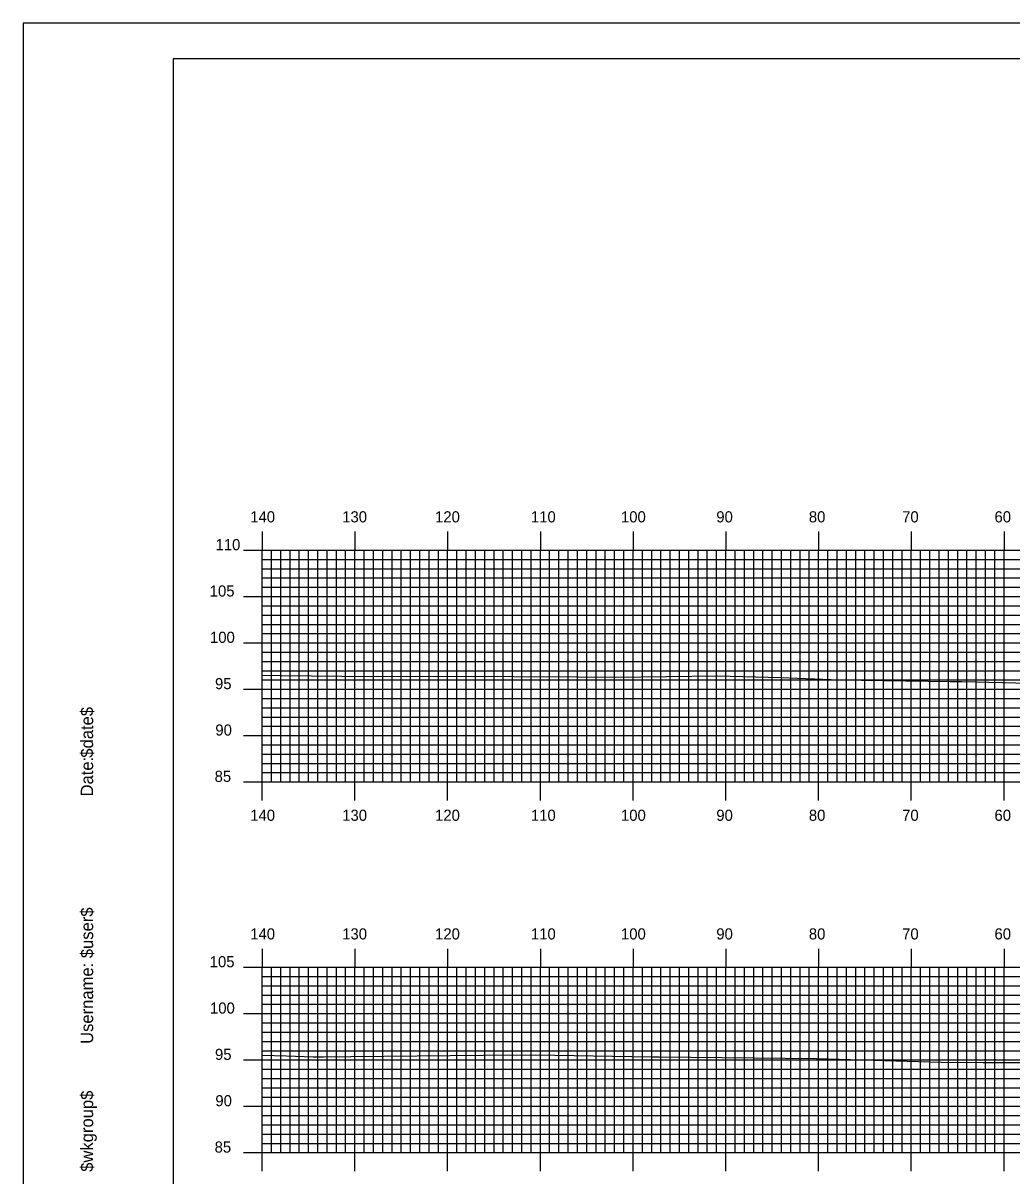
# Model space of a CAD drawing. Extents: x 1764152 to 1764495, y 442591 to 442811.
# Drawn here: x 1764152 to 1764258.7, y 442686.2 to 442810.5 of the extents above; entities that cross this region are included whole.
import ezdxf

# ---------------------------------------------------------------- set-up
doc = ezdxf.new("R2010")
doc.units = 0
for name, color, linetype in [('BORDER', 7, 'Continuous'), ('H_V ANNOTATION', 7, 'Continuous'), ('MAJOR', 7, 'Continuous'), ('MINOR', 7, 'Continuous'), ('PLOT BOUNDARY', 7, 'Continuous'), ('S_Roadway_Centerline', 7, 'Continuous')]:
    doc.layers.add(name, color=color, linetype=linetype)

msp = doc.modelspace()

# ---------------------------------------------------------------- linework, layer by layer
at = {"layer": 'BORDER'}
msp.add_lwpolyline([(1764168.23, 442596.67), (1764488.23, 442596.67), (1764488.23, 442806.67), (1764168.23, 442806.67)], close=True, dxfattribs=at)
at = {"layer": 'MAJOR'}
for p, q in [((1764177.83, 442755.67), (1764177.83, 442753.67)), ((1764187.83, 442755.67), (1764187.83, 442753.67)), ((1764197.83, 442755.67), (1764197.83, 442753.67)), ((1764207.83, 442755.67), (1764207.83, 442753.67)), ((1764217.83, 442755.67), (1764217.83, 442753.67)), ((1764227.83, 442755.67), (1764227.83, 442753.67)), ((1764237.83, 442755.67), (1764237.83, 442753.67)), ((1764247.83, 442755.67), (1764247.83, 442753.67)), ((1764257.83, 442755.67), (1764257.83, 442753.67)), ((1764175.83, 442753.67), (1764177.83, 442753.67)), ((1764177.83, 442753.67), (1764457.83, 442753.67)), ((1764177.83, 442728.67), (1764177.83, 442753.67)), ((1764177.83, 442728.67), (1764177.83, 442753.67)), ((1764177.83, 442753.67), (1764457.83, 442753.67)), ((1764187.83, 442728.67), (1764187.83, 442753.67)), ((1764197.83, 442728.67), (1764197.83, 442753.67)), ((1764207.83, 442728.67), (1764207.83, 442753.67)), ((1764217.83, 442728.67), (1764217.83, 442753.67)), ((1764227.83, 442728.67), (1764227.83, 442753.67)), ((1764237.83, 442728.67), (1764237.83, 442753.67)), ((1764247.83, 442728.67), (1764247.83, 442753.67)), ((1764257.83, 442728.67), (1764257.83, 442753.67)), ((1764175.83, 442748.67), (1764177.83, 442748.67)), ((1764177.83, 442748.67), (1764457.83, 442748.67)), ((1764175.83, 442743.67), (1764177.83, 442743.67)), ((1764177.83, 442743.67), (1764457.83, 442743.67)), ((1764175.83, 442738.67), (1764177.83, 442738.67)), ((1764177.83, 442738.67), (1764457.83, 442738.67)), ((1764175.83, 442733.67), (1764177.83, 442733.67)), ((1764177.83, 442733.67), (1764457.83, 442733.67)), ((1764175.83, 442728.67), (1764177.83, 442728.67)), ((1764177.83, 442728.67), (1764457.83, 442728.67)), ((1764177.83, 442728.67), (1764457.83, 442728.67)), ((1764177.83, 442726.66), (1764177.83, 442728.67)), ((1764187.83, 442726.66), (1764187.83, 442728.67)), ((1764197.83, 442726.66), (1764197.83, 442728.67)), ((1764207.83, 442726.66), (1764207.83, 442728.67)), ((1764217.83, 442726.66), (1764217.83, 442728.67)), ((1764227.83, 442726.66), (1764227.83, 442728.67)), ((1764237.83, 442726.66), (1764237.83, 442728.67)), ((1764247.83, 442726.66), (1764247.83, 442728.67)), ((1764257.83, 442726.66), (1764257.83, 442728.67)), ((1764177.83, 442710.67), (1764177.83, 442708.67)), ((1764187.83, 442710.67), (1764187.83, 442708.67)), ((1764197.83, 442710.67), (1764197.83, 442708.67)), ((1764207.83, 442710.67), (1764207.83, 442708.67)), ((1764217.83, 442710.67), (1764217.83, 442708.67)), ((1764227.83, 442710.67), (1764227.83, 442708.67)), ((1764237.83, 442710.67), (1764237.83, 442708.67)), ((1764247.83, 442710.67), (1764247.83, 442708.67)), ((1764257.83, 442710.67), (1764257.83, 442708.67)), ((1764175.83, 442708.67), (1764177.83, 442708.67)), ((1764177.83, 442708.67), (1764457.83, 442708.67)), ((1764177.83, 442688.67), (1764177.83, 442708.67)), ((1764177.83, 442688.67), (1764177.83, 442708.67)), ((1764177.83, 442708.67), (1764457.83, 442708.67)), ((1764187.83, 442688.67), (1764187.83, 442708.67)), ((1764197.83, 442688.67), (1764197.83, 442708.67)), ((1764207.83, 442688.67), (1764207.83, 442708.67)), ((1764217.83, 442688.67), (1764217.83, 442708.67)), ((1764227.83, 442688.67), (1764227.83, 442708.67)), ((1764237.83, 442688.67), (1764237.83, 442708.67)), ((1764247.83, 442688.67), (1764247.83, 442708.67)), ((1764257.83, 442688.67), (1764257.83, 442708.67)), ((1764175.83, 442703.67), (1764177.83, 442703.67)), ((1764177.83, 442703.67), (1764457.83, 442703.67)), ((1764175.83, 442698.67), (1764177.83, 442698.67)), ((1764177.83, 442698.67), (1764457.83, 442698.67)), ((1764175.83, 442693.67), (1764177.83, 442693.67)), ((1764177.83, 442693.67), (1764457.83, 442693.67)), ((1764175.83, 442688.67), (1764177.83, 442688.67)), ((1764177.83, 442688.67), (1764457.83, 442688.67)), ((1764177.83, 442688.67), (1764457.83, 442688.67)), ((1764177.83, 442686.66), (1764177.83, 442688.67)), ((1764187.83, 442686.66), (1764187.83, 442688.67)), ((1764197.83, 442686.66), (1764197.83, 442688.67)), ((1764207.83, 442686.66), (1764207.83, 442688.67)), ((1764217.83, 442686.66), (1764217.83, 442688.67)), ((1764227.83, 442686.66), (1764227.83, 442688.67)), ((1764237.83, 442686.66), (1764237.83, 442688.67)), ((1764247.83, 442686.66), (1764247.83, 442688.67)), ((1764257.83, 442686.66), (1764257.83, 442688.67))]:
    msp.add_line(p, q, dxfattribs=at)
at = {"layer": 'MINOR'}
for p, q in [((1764178.83, 442728.67), (1764178.83, 442753.67)), ((1764179.83, 442728.67), (1764179.83, 442753.67)), ((1764180.83, 442728.67), (1764180.83, 442753.67)), ((1764181.83, 442728.67), (1764181.83, 442753.67)), ((1764182.83, 442728.67), (1764182.83, 442753.67)), ((1764183.83, 442728.67), (1764183.83, 442753.67)), ((1764184.83, 442728.67), (1764184.83, 442753.67)), ((1764185.83, 442728.67), (1764185.83, 442753.67)), ((1764186.83, 442728.67), (1764186.83, 442753.67)), ((1764188.83, 442728.67), (1764188.83, 442753.67)), ((1764189.83, 442728.67), (1764189.83, 442753.67)), ((1764190.83, 442728.67), (1764190.83, 442753.67)), ((1764191.83, 442728.67), (1764191.83, 442753.67)), ((1764192.83, 442728.67), (1764192.83, 442753.67)), ((1764193.83, 442728.67), (1764193.83, 442753.67)), ((1764194.83, 442728.67), (1764194.83, 442753.67)), ((1764195.83, 442728.67), (1764195.83, 442753.67)), ((1764196.83, 442728.67), (1764196.83, 442753.67)), ((1764198.83, 442728.67), (1764198.83, 442753.67)), ((1764199.83, 442728.67), (1764199.83, 442753.67)), ((1764200.83, 442728.67), (1764200.83, 442753.67)), ((1764201.83, 442728.67), (1764201.83, 442753.67)), ((1764202.83, 442728.67), (1764202.83, 442753.67)), ((1764203.83, 442728.67), (1764203.83, 442753.67)), ((1764204.83, 442728.67), (1764204.83, 442753.67)), ((1764205.83, 442728.67), (1764205.83, 442753.67)), ((1764206.83, 442728.67), (1764206.83, 442753.67)), ((1764208.83, 442728.67), (1764208.83, 442753.67)), ((1764209.83, 442728.67), (1764209.83, 442753.67)), ((1764210.83, 442728.67), (1764210.83, 442753.67)), ((1764211.83, 442728.67), (1764211.83, 442753.67)), ((1764212.83, 442728.67), (1764212.83, 442753.67)), ((1764213.83, 442728.67), (1764213.83, 442753.67)), ((1764214.83, 442728.67), (1764214.83, 442753.67)), ((1764215.83, 442728.67), (1764215.83, 442753.67)), ((1764216.83, 442728.67), (1764216.83, 442753.67)), ((1764218.83, 442728.67), (1764218.83, 442753.67)), ((1764219.83, 442728.67), (1764219.83, 442753.67)), ((1764220.83, 442728.67), (1764220.83, 442753.67)), ((1764221.83, 442728.67), (1764221.83, 442753.67)), ((1764222.83, 442728.67), (1764222.83, 442753.67)), ((1764223.83, 442728.67), (1764223.83, 442753.67)), ((1764224.83, 442728.67), (1764224.83, 442753.67)), ((1764225.83, 442728.67), (1764225.83, 442753.67)), ((1764226.83, 442728.67), (1764226.83, 442753.67)), ((1764228.83, 442728.67), (1764228.83, 442753.67)), ((1764229.83, 442728.67), (1764229.83, 442753.67)), ((1764230.83, 442728.67), (1764230.83, 442753.67)), ((1764231.83, 442728.67), (1764231.83, 442753.67)), ((1764232.83, 442728.67), (1764232.83, 442753.67)), ((1764233.83, 442728.67), (1764233.83, 442753.67)), ((1764234.83, 442728.67), (1764234.83, 442753.67)), ((1764235.83, 442728.67), (1764235.83, 442753.67)), ((1764236.83, 442728.67), (1764236.83, 442753.67)), ((1764238.83, 442728.67), (1764238.83, 442753.67)), ((1764239.83, 442728.67), (1764239.83, 442753.67)), ((1764240.83, 442728.67), (1764240.83, 442753.67)), ((1764241.83, 442728.67), (1764241.83, 442753.67)), ((1764242.83, 442728.67), (1764242.83, 442753.67)), ((1764243.83, 442728.67), (1764243.83, 442753.67)), ((1764244.83, 442728.67), (1764244.83, 442753.67)), ((1764245.83, 442728.67), (1764245.83, 442753.67)), ((1764246.83, 442728.67), (1764246.83, 442753.67)), ((1764248.83, 442728.67), (1764248.83, 442753.67)), ((1764249.83, 442728.67), (1764249.83, 442753.67)), ((1764250.83, 442728.67), (1764250.83, 442753.67)), ((1764251.83, 442728.67), (1764251.83, 442753.67)), ((1764252.83, 442728.67), (1764252.83, 442753.67)), ((1764253.83, 442728.67), (1764253.83, 442753.67)), ((1764254.83, 442728.67), (1764254.83, 442753.67)), ((1764255.83, 442728.67), (1764255.83, 442753.67)), ((1764256.83, 442728.67), (1764256.83, 442753.67)), ((1764177.83, 442752.67), (1764457.83, 442752.67)), ((1764177.83, 442752.67), (1764179.84, 442752.67)), ((1764177.83, 442751.67), (1764457.83, 442751.67)), ((1764177.83, 442751.67), (1764179.84, 442751.67)), ((1764177.83, 442750.67), (1764457.83, 442750.67)), ((1764177.83, 442750.67), (1764179.84, 442750.67)), ((1764177.83, 442749.67), (1764457.83, 442749.67)), ((1764177.83, 442749.67), (1764179.84, 442749.67)), ((1764177.83, 442747.67), (1764457.83, 442747.67)), ((1764177.83, 442747.67), (1764179.84, 442747.67)), ((1764177.83, 442746.67), (1764457.83, 442746.67)), ((1764177.83, 442746.67), (1764179.84, 442746.67)), ((1764177.83, 442745.67), (1764457.83, 442745.67)), ((1764177.83, 442745.67), (1764179.84, 442745.67)), ((1764177.83, 442744.67), (1764457.83, 442744.67)), ((1764177.83, 442744.67), (1764179.84, 442744.67)), ((1764177.83, 442742.67), (1764457.83, 442742.67)), ((1764177.83, 442742.67), (1764179.84, 442742.67)), ((1764177.83, 442741.67), (1764457.83, 442741.67)), ((1764177.83, 442741.67), (1764179.84, 442741.67)), ((1764177.83, 442740.67), (1764457.83, 442740.67)), ((1764177.83, 442740.67), (1764179.84, 442740.67)), ((1764177.83, 442739.67), (1764457.83, 442739.67)), ((1764177.83, 442739.67), (1764179.84, 442739.67)), ((1764177.83, 442737.67), (1764457.83, 442737.67)), ((1764177.83, 442737.67), (1764179.84, 442737.67)), ((1764177.83, 442736.67), (1764457.83, 442736.67)), ((1764177.83, 442736.67), (1764179.84, 442736.67)), ((1764177.83, 442735.67), (1764457.83, 442735.67)), ((1764177.83, 442735.67), (1764179.84, 442735.67)), ((1764177.83, 442734.67), (1764457.83, 442734.67)), ((1764177.83, 442734.67), (1764179.84, 442734.67)), ((1764177.83, 442732.67), (1764457.83, 442732.67)), ((1764177.83, 442732.67), (1764179.84, 442732.67)), ((1764177.83, 442731.67), (1764457.83, 442731.67)), ((1764177.83, 442731.67), (1764179.84, 442731.67)), ((1764177.83, 442730.67), (1764457.83, 442730.67)), ((1764177.83, 442730.67), (1764179.84, 442730.67)), ((1764177.83, 442729.67), (1764457.83, 442729.67)), ((1764177.83, 442729.67), (1764179.84, 442729.67)), ((1764178.83, 442688.67), (1764178.83, 442708.67)), ((1764179.83, 442688.67), (1764179.83, 442708.67)), ((1764180.83, 442688.67), (1764180.83, 442708.67)), ((1764181.83, 442688.67), (1764181.83, 442708.67)), ((1764182.83, 442688.67), (1764182.83, 442708.67)), ((1764183.83, 442688.67), (1764183.83, 442708.67)), ((1764184.83, 442688.67), (1764184.83, 442708.67)), ((1764185.83, 442688.67), (1764185.83, 442708.67)), ((1764186.83, 442688.67), (1764186.83, 442708.67)), ((1764188.83, 442688.67), (1764188.83, 442708.67)), ((1764189.83, 442688.67), (1764189.83, 442708.67)), ((1764190.83, 442688.67), (1764190.83, 442708.67)), ((1764191.83, 442688.67), (1764191.83, 442708.67)), ((1764192.83, 442688.67), (1764192.83, 442708.67)), ((1764193.83, 442688.67), (1764193.83, 442708.67)), ((1764194.83, 442688.67), (1764194.83, 442708.67)), ((1764195.83, 442688.67), (1764195.83, 442708.67)), ((1764196.83, 442688.67), (1764196.83, 442708.67)), ((1764198.83, 442688.67), (1764198.83, 442708.67)), ((1764199.83, 442688.67), (1764199.83, 442708.67)), ((1764200.83, 442688.67), (1764200.83, 442708.67)), ((1764201.83, 442688.67), (1764201.83, 442708.67)), ((1764202.83, 442688.67), (1764202.83, 442708.67)), ((1764203.83, 442688.67), (1764203.83, 442708.67)), ((1764204.83, 442688.67), (1764204.83, 442708.67)), ((1764205.83, 442688.67), (1764205.83, 442708.67)), ((1764206.83, 442688.67), (1764206.83, 442708.67)), ((1764208.83, 442688.67), (1764208.83, 442708.67)), ((1764209.83, 442688.67), (1764209.83, 442708.67)), ((1764210.83, 442688.67), (1764210.83, 442708.67)), ((1764211.83, 442688.67), (1764211.83, 442708.67)), ((1764212.83, 442688.67), (1764212.83, 442708.67)), ((1764213.83, 442688.67), (1764213.83, 442708.67)), ((1764214.83, 442688.67), (1764214.83, 442708.67)), ((1764215.83, 442688.67), (1764215.83, 442708.67)), ((1764216.83, 442688.67), (1764216.83, 442708.67)), ((1764218.83, 442688.67), (1764218.83, 442708.67)), ((1764219.83, 442688.67), (1764219.83, 442708.67)), ((1764220.83, 442688.67), (1764220.83, 442708.67)), ((1764221.83, 442688.67), (1764221.83, 442708.67)), ((1764222.83, 442688.67), (1764222.83, 442708.67)), ((1764223.83, 442688.67), (1764223.83, 442708.67)), ((1764224.83, 442688.67), (1764224.83, 442708.67)), ((1764225.83, 442688.67), (1764225.83, 442708.67)), ((1764226.83, 442688.67), (1764226.83, 442708.67)), ((1764228.83, 442688.67), (1764228.83, 442708.67)), ((1764229.83, 442688.67), (1764229.83, 442708.67)), ((1764230.83, 442688.67), (1764230.83, 442708.67)), ((1764231.83, 442688.67), (1764231.83, 442708.67)), ((1764232.83, 442688.67), (1764232.83, 442708.67)), ((1764233.83, 442688.67), (1764233.83, 442708.67)), ((1764234.83, 442688.67), (1764234.83, 442708.67)), ((1764235.83, 442688.67), (1764235.83, 442708.67)), ((1764236.83, 442688.67), (1764236.83, 442708.67)), ((1764238.83, 442688.67), (1764238.83, 442708.67)), ((1764239.83, 442688.67), (1764239.83, 442708.67)), ((1764240.83, 442688.67), (1764240.83, 442708.67)), ((1764241.83, 442688.67), (1764241.83, 442708.67)), ((1764242.83, 442688.67), (1764242.83, 442708.67)), ((1764243.83, 442688.67), (1764243.83, 442708.67)), ((1764244.83, 442688.67), (1764244.83, 442708.67)), ((1764245.83, 442688.67), (1764245.83, 442708.67)), ((1764246.83, 442688.67), (1764246.83, 442708.67)), ((1764248.83, 442688.67), (1764248.83, 442708.67)), ((1764249.83, 442688.67), (1764249.83, 442708.67)), ((1764250.83, 442688.67), (1764250.83, 442708.67)), ((1764251.83, 442688.67), (1764251.83, 442708.67)), ((1764252.83, 442688.67), (1764252.83, 442708.67)), ((1764253.83, 442688.67), (1764253.83, 442708.67)), ((1764254.83, 442688.67), (1764254.83, 442708.67)), ((1764255.83, 442688.67), (1764255.83, 442708.67)), ((1764256.83, 442688.67), (1764256.83, 442708.67)), ((1764177.83, 442707.67), (1764457.83, 442707.67)), ((1764177.83, 442707.67), (1764179.84, 442707.67)), ((1764177.83, 442706.67), (1764457.83, 442706.67)), ((1764177.83, 442706.67), (1764179.84, 442706.67)), ((1764177.83, 442705.67), (1764457.83, 442705.67)), ((1764177.83, 442705.67), (1764179.84, 442705.67)), ((1764177.83, 442704.67), (1764457.83, 442704.67)), ((1764177.83, 442704.67), (1764179.84, 442704.67)), ((1764177.83, 442702.67), (1764457.83, 442702.67)), ((1764177.83, 442702.67), (1764179.84, 442702.67)), ((1764177.83, 442701.67), (1764457.83, 442701.67)), ((1764177.83, 442701.67), (1764179.84, 442701.67)), ((1764177.83, 442700.67), (1764457.83, 442700.67)), ((1764177.83, 442700.67), (1764179.84, 442700.67)), ((1764177.83, 442699.67), (1764457.83, 442699.67)), ((1764177.83, 442699.67), (1764179.84, 442699.67)), ((1764177.83, 442697.67), (1764457.83, 442697.67)), ((1764177.83, 442697.67), (1764179.84, 442697.67)), ((1764177.83, 442696.67), (1764457.83, 442696.67)), ((1764177.83, 442696.67), (1764179.84, 442696.67)), ((1764177.83, 442695.67), (1764457.83, 442695.67)), ((1764177.83, 442695.67), (1764179.84, 442695.67)), ((1764177.83, 442694.67), (1764457.83, 442694.67)), ((1764177.83, 442694.67), (1764179.84, 442694.67)), ((1764177.83, 442692.67), (1764457.83, 442692.67)), ((1764177.83, 442692.67), (1764179.84, 442692.67)), ((1764177.83, 442691.67), (1764457.83, 442691.67)), ((1764177.83, 442691.67), (1764179.84, 442691.67)), ((1764177.83, 442690.67), (1764457.83, 442690.67)), ((1764177.83, 442690.67), (1764179.84, 442690.67)), ((1764177.83, 442689.67), (1764457.83, 442689.67)), ((1764177.83, 442689.67), (1764179.84, 442689.67))]:
    msp.add_line(p, q, dxfattribs=at)
at = {"layer": 'PLOT BOUNDARY'}
msp.add_lwpolyline([(1764152.04, 442590.55), (1764492.04, 442590.55), (1764492.04, 442810.55), (1764152.04, 442810.55)], close=True, dxfattribs=at)
at = {"layer": 'S_Roadway_Centerline'}
for points in [[(1764177.83, 442740.17), (1764179.92, 442740.15), (1764189.67, 442740.03), (1764198, 442740.06), (1764211.91, 442740), (1764215.93, 442739.98), (1764226.93, 442740.12), (1764233.77, 442739.93), (1764240.08, 442739.68), (1764252.01, 442739.52), (1764252.39, 442739.51), (1764253.29, 442739.49), (1764269.32, 442739.11)], [(1764177.83, 442699.2), (1764180.44, 442699.12), (1764183.32, 442699.01), (1764184.44, 442699), (1764187.38, 442699.05), (1764201.69, 442699.19), (1764207.29, 442699.23), (1764219.76, 442699.02), (1764220.04, 442699.02), (1764220.67, 442699.01), (1764237.59, 442698.82), (1764251.04, 442698.43), (1764255.59, 442698.38), (1764261.16, 442698.41)]]:
    msp.add_lwpolyline(points, dxfattribs=at)

# ---------------------------------------------------------------- texts
at = {"layer": 'BORDER'}
for s, p in [('$date$', (1764159.6, 442731.28)), ('Date:', (1764159.6, 442727.1)), ('$user$', (1764159.6, 442709.65)), ('Username:', (1764159.6, 442700.4)), ('$wkgroup$', (1764159.6, 442686.6))]:
    msp.add_text(s, height=1.339, rotation=90, dxfattribs=at).set_placement(p)
at = {"layer": 'H_V ANNOTATION'}
for s, p in [('140', (1764176.54, 442756.67)), ('130', (1764186.46, 442756.67)), ('120', (1764196.47, 442756.67)), ('110', (1764206.81, 442756.67)), ('100', (1764216.52, 442756.67)), ('90', (1764226.8, 442756.67)), ('80', (1764236.78, 442756.67)), ('70', (1764246.84, 442756.67)), ('60', (1764256.8, 442756.67)), ('110', (1764172.8, 442753.67)), ('105', (1764172.17, 442748.67)), ('100', (1764172.2, 442743.67)), ('95', (1764172.74, 442738.67)), ('90', (1764172.78, 442733.67)), ('85', (1764172.7, 442728.67)), ('140', (1764176.54, 442724.47)), ('130', (1764186.46, 442724.47)), ('120', (1764196.47, 442724.47)), ('110', (1764206.81, 442724.47)), ('100', (1764216.52, 442724.47)), ('90', (1764226.8, 442724.47)), ('80', (1764236.78, 442724.47)), ('70', (1764246.84, 442724.47)), ('60', (1764256.8, 442724.47)), ('140', (1764176.54, 442711.67)), ('130', (1764186.46, 442711.67)), ('120', (1764196.47, 442711.67)), ('110', (1764206.81, 442711.67)), ('100', (1764216.52, 442711.67)), ('90', (1764226.8, 442711.67)), ('80', (1764236.78, 442711.67)), ('70', (1764246.84, 442711.67)), ('60', (1764256.8, 442711.67)), ('105', (1764172.17, 442708.67)), ('100', (1764172.2, 442703.67)), ('95', (1764172.74, 442698.67)), ('90', (1764172.78, 442693.67)), ('85', (1764172.7, 442688.67))]:
    msp.add_text(s, height=1.2, dxfattribs=at).set_placement(p)
at = {"layer": 'MAJOR'}
for p in [(1764177.82, 442728.67), (1764177.82, 442688.67)]:
    msp.add_text('-', height=0.012, dxfattribs=at).set_placement(p)

doc.saveas('drawing.dxf')
